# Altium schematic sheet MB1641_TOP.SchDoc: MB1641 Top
size A4; Date: Not used; ApprovedBy: Not used; CheckedBy: Not used; Author: Not used; CompanyName: STMicroelectronics; DrawnBy: Not used; Engineer: Not used; Organization: Not used; Address1: Not used; Address2: Not used; Address3: Not used; Address4: Not used; DocumentNumber: Not used; Revision: Not used; SheetNumber: 2; SheetTotal: 8
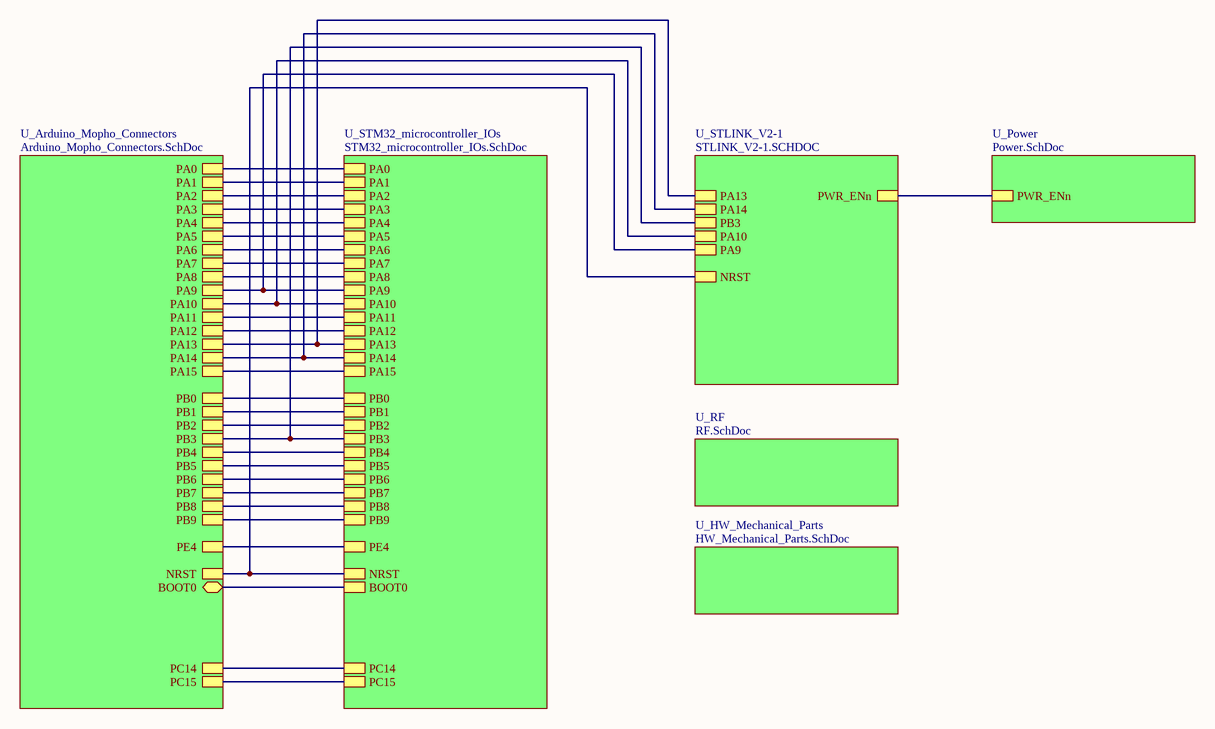
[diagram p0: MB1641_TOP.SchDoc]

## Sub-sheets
U_Arduino_Mopho_Connectors = Arduino_Mopho_Connectors.SchDoc: NRST, BOOT0 (bidir), PC14, PC15, PB4, PB8, PB9, PA4, PA9, PA3, PA2, PA0, PA5, PA6, PA7, PA8, PA15, PB0, PA10, PE4, PB1, PB5, PA11, PA12, PA13, PA14, PB2, PB3, PB6, PB7, PA1
U_HW_Mechanical_Parts = HW_Mechanical_Parts.SchDoc: no entries
U_Power = Power.SchDoc: PWR_ENn
U_RF = RF.SchDoc: no entries
U_STLINK_V2-1 = STLINK_V2-1.SCHDOC: NRST, PA13, PA14, PB3, PWR_ENn, PA10, PA9
U_STM32_microcontroller_IOs = STM32_microcontroller_IOs.SchDoc: PA13, PA14, PA15, PB3, PB4, PA11, PA12, PA0, PA1, PA2, PA3, PA4, PA5, PA6, PA7, PA8, PA9, PA10, PB2, PB5, PB6, PB7, PB8, PB9, NRST, BOOT0, PC14, PC15, PB1, PB0, PE4

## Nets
(unnamed): sheet U_Power/PWR_ENn, sheet U_STLINK_V2-1/PWR_ENn
(unnamed): sheet U_STLINK_V2-1/NRST, sheet U_Arduino_Mopho_Connectors/NRST, sheet U_STM32_microcontroller_IOs/NRST  [a separate net that carries the same name]
(unnamed): sheet U_STLINK_V2-1/PA13, sheet U_Arduino_Mopho_Connectors/PA13, sheet U_STM32_microcontroller_IOs/PA13  [a separate net that carries the same name]
(unnamed): sheet U_STLINK_V2-1/PA14, sheet U_Arduino_Mopho_Connectors/PA14, sheet U_STM32_microcontroller_IOs/PA14  [a separate net that carries the same name]
(unnamed): sheet U_STLINK_V2-1/PB3, sheet U_Arduino_Mopho_Connectors/PB3, sheet U_STM32_microcontroller_IOs/PB3  [a separate net that carries the same name]
(unnamed): sheet U_STLINK_V2-1/PA10, sheet U_Arduino_Mopho_Connectors/PA10, sheet U_STM32_microcontroller_IOs/PA10  [a separate net that carries the same name]
(unnamed): sheet U_STLINK_V2-1/PA9, sheet U_Arduino_Mopho_Connectors/PA9, sheet U_STM32_microcontroller_IOs/PA9  [a separate net that carries the same name]
(unnamed): sheet U_Arduino_Mopho_Connectors/BOOT0, sheet U_STM32_microcontroller_IOs/BOOT0  [a separate net that carries the same name]
(unnamed): sheet U_Arduino_Mopho_Connectors/PC14, sheet U_STM32_microcontroller_IOs/PC14  [a separate net that carries the same name]
(unnamed): sheet U_Arduino_Mopho_Connectors/PC15, sheet U_STM32_microcontroller_IOs/PC15  [a separate net that carries the same name]
(unnamed): sheet U_Arduino_Mopho_Connectors/PB4, sheet U_STM32_microcontroller_IOs/PB4  [a separate net that carries the same name]
(unnamed): sheet U_Arduino_Mopho_Connectors/PB8, sheet U_STM32_microcontroller_IOs/PB8  [a separate net that carries the same name]
(unnamed): sheet U_Arduino_Mopho_Connectors/PB9, sheet U_STM32_microcontroller_IOs/PB9  [a separate net that carries the same name]
(unnamed): sheet U_Arduino_Mopho_Connectors/PA4, sheet U_STM32_microcontroller_IOs/PA4  [a separate net that carries the same name]
(unnamed): sheet U_Arduino_Mopho_Connectors/PA3, sheet U_STM32_microcontroller_IOs/PA3  [a separate net that carries the same name]
(unnamed): sheet U_Arduino_Mopho_Connectors/PA2, sheet U_STM32_microcontroller_IOs/PA2  [a separate net that carries the same name]
(unnamed): sheet U_Arduino_Mopho_Connectors/PA0, sheet U_STM32_microcontroller_IOs/PA0  [a separate net that carries the same name]
(unnamed): sheet U_Arduino_Mopho_Connectors/PA5, sheet U_STM32_microcontroller_IOs/PA5  [a separate net that carries the same name]
(unnamed): sheet U_Arduino_Mopho_Connectors/PA6, sheet U_STM32_microcontroller_IOs/PA6  [a separate net that carries the same name]
(unnamed): sheet U_Arduino_Mopho_Connectors/PA7, sheet U_STM32_microcontroller_IOs/PA7  [a separate net that carries the same name]
(unnamed): sheet U_Arduino_Mopho_Connectors/PA8, sheet U_STM32_microcontroller_IOs/PA8  [a separate net that carries the same name]
(unnamed): sheet U_Arduino_Mopho_Connectors/PA15, sheet U_STM32_microcontroller_IOs/PA15  [a separate net that carries the same name]
(unnamed): sheet U_Arduino_Mopho_Connectors/PB0, sheet U_STM32_microcontroller_IOs/PB0  [a separate net that carries the same name]
(unnamed): sheet U_Arduino_Mopho_Connectors/PE4, sheet U_STM32_microcontroller_IOs/PE4  [a separate net that carries the same name]
(unnamed): sheet U_Arduino_Mopho_Connectors/PB1, sheet U_STM32_microcontroller_IOs/PB1  [a separate net that carries the same name]
(unnamed): sheet U_Arduino_Mopho_Connectors/PB5, sheet U_STM32_microcontroller_IOs/PB5  [a separate net that carries the same name]
(unnamed): sheet U_Arduino_Mopho_Connectors/PA11, sheet U_STM32_microcontroller_IOs/PA11  [a separate net that carries the same name]
(unnamed): sheet U_Arduino_Mopho_Connectors/PA12, sheet U_STM32_microcontroller_IOs/PA12  [a separate net that carries the same name]
(unnamed): sheet U_Arduino_Mopho_Connectors/PB2, sheet U_STM32_microcontroller_IOs/PB2  [a separate net that carries the same name]
(unnamed): sheet U_Arduino_Mopho_Connectors/PB6, sheet U_STM32_microcontroller_IOs/PB6  [a separate net that carries the same name]
(unnamed): sheet U_Arduino_Mopho_Connectors/PB7, sheet U_STM32_microcontroller_IOs/PB7  [a separate net that carries the same name]
(unnamed): sheet U_Arduino_Mopho_Connectors/PA1, sheet U_STM32_microcontroller_IOs/PA1  [a separate net that carries the same name]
